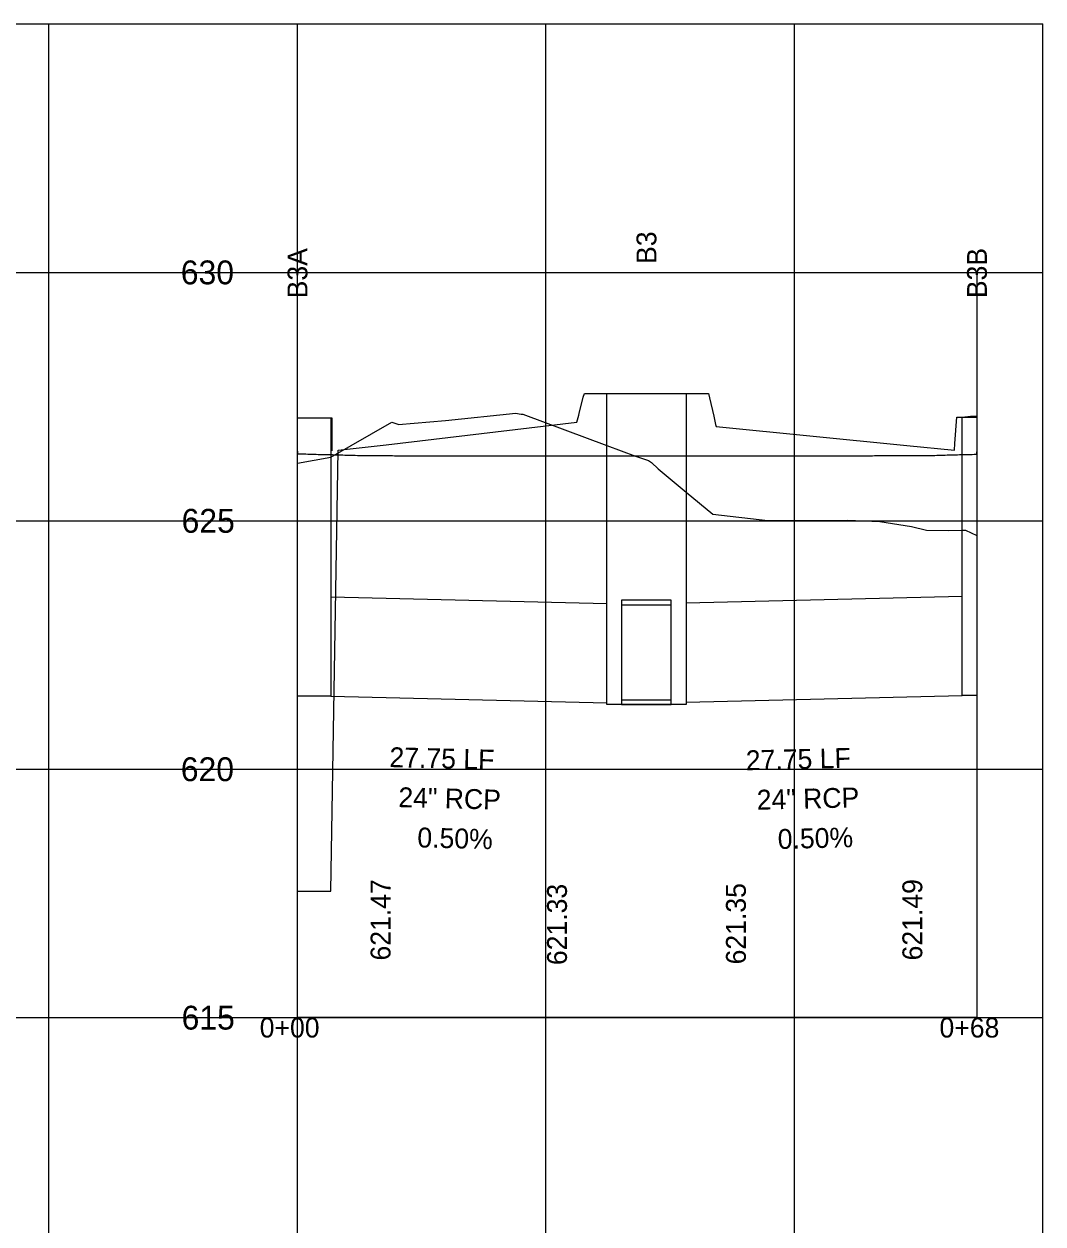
# Model space of a CAD drawing. Extents: x 2254979 to 2278074, y 13790855 to 13792793.
# Drawn here: x 2276971.9 to 2277074.4, y 13792671.8 to 13792792.6 of the extents above; entities that cross this region are included whole.
import ezdxf

# ---------------------------------------------------------------- set-up
doc = ezdxf.new("R2010")
doc.units = 0
for name, color, linetype in [('blank4', 7, 'Continuous'), ('BORD_grid_bottom_major_5int', 7, 'Continuous'), ('D_DRN_PROF_HGL', 7, 'Continuous'), ('D_PROF_1', 7, 'Continuous'), ('D_PROF_NOTES_1', 7, 'Continuous'), ('Default', 7, 'Continuous'), ('Drain_PipeInside', 7, 'Continuous'), ('E_Terrain', 7, 'Continuous'), ('Inlet', 7, 'Continuous'), ('z - Construction', 7, 'Continuous')]:
    doc.layers.add(name, color=color, linetype=linetype)

msp = doc.modelspace()

# ---------------------------------------------------------------- linework, layer by layer
at = {"layer": 'blank4'}
msp.add_lwpolyline([(2276999.4, 13792692.6), (2276999.4, 13792767.6), (2277067.76, 13792767.6), (2277067.76, 13792692.6)], close=True, dxfattribs=at)
at = {"layer": 'BORD_grid_bottom_major_5int'}
for p, q in [((2276749.4, 13792792.6), (2277074.4, 13792792.6)), ((2276974.4, 13792492.6), (2276974.4, 13792792.6)), ((2276999.4, 13792492.6), (2276999.4, 13792792.6)), ((2277024.4, 13792492.6), (2277024.4, 13792792.6)), ((2277049.4, 13792492.6), (2277049.4, 13792792.6)), ((2277074.4, 13792492.6), (2277074.4, 13792792.6)), ((2276749.4, 13792767.6), (2277074.4, 13792767.6)), ((2276749.4, 13792742.6), (2277074.4, 13792742.6)), ((2276749.4, 13792717.6), (2277074.4, 13792717.6)), ((2276749.4, 13792692.6), (2277074.4, 13792692.6))]:
    msp.add_line(p, q, dxfattribs=at)
at = {"layer": 'D_DRN_PROF_HGL'}
msp.add_line((2277034.51, 13792749.13), (2277034.51, 13792749.13), dxfattribs=at)
for points in [[(2276999.4, 13792749.62), (2276999.4, 13792749.35), (2276999.61, 13792749.34), (2276999.82, 13792749.34), (2277000.03, 13792749.33), (2277000.23, 13792749.33), (2277000.44, 13792749.32), (2277000.65, 13792749.32), (2277000.86, 13792749.31), (2277001.07, 13792749.3), (2277001.27, 13792749.3), (2277001.48, 13792749.29), (2277001.69, 13792749.29), (2277001.9, 13792749.28), (2277002.1, 13792749.28), (2277002.31, 13792749.27), (2277002.52, 13792749.27), (2277002.73, 13792749.26), (2277002.93, 13792749.26), (2277003.14, 13792749.25), (2277003.35, 13792749.25), (2277003.56, 13792749.24), (2277003.77, 13792749.23), (2277003.97, 13792749.23), (2277004.18, 13792749.22), (2277004.39, 13792749.22), (2277004.6, 13792749.21), (2277004.8, 13792749.21), (2277005.01, 13792749.2), (2277005.22, 13792749.2), (2277005.43, 13792749.19), (2277005.64, 13792749.19), (2277005.84, 13792749.18), (2277006.05, 13792749.18), (2277006.26, 13792749.17), (2277006.47, 13792749.16), (2277006.67, 13792749.16), (2277006.88, 13792749.16), (2277007.09, 13792749.16), (2277007.3, 13792749.16), (2277007.5, 13792749.16), (2277007.71, 13792749.16), (2277007.92, 13792749.16), (2277008.13, 13792749.16), (2277008.34, 13792749.16), (2277008.54, 13792749.16), (2277008.75, 13792749.16), (2277008.96, 13792749.16), (2277009.17, 13792749.15), (2277009.37, 13792749.15), (2277009.58, 13792749.15), (2277009.79, 13792749.15), (2277010, 13792749.15), (2277010.21, 13792749.15), (2277010.41, 13792749.15), (2277010.62, 13792749.15), (2277010.83, 13792749.15), (2277011.04, 13792749.15), (2277011.24, 13792749.15), (2277011.45, 13792749.15), (2277011.66, 13792749.15), (2277011.87, 13792749.15), (2277012.07, 13792749.15), (2277012.28, 13792749.15), (2277012.49, 13792749.15), (2277012.7, 13792749.15), (2277012.91, 13792749.15), (2277013.11, 13792749.15), (2277013.32, 13792749.15), (2277013.53, 13792749.15), (2277013.74, 13792749.15), (2277013.94, 13792749.15), (2277014.15, 13792749.15), (2277014.36, 13792749.15), (2277014.57, 13792749.15), (2277014.78, 13792749.15), (2277014.98, 13792749.15), (2277015.19, 13792749.15), (2277015.4, 13792749.15), (2277015.61, 13792749.15), (2277015.81, 13792749.15), (2277016.02, 13792749.15), (2277016.23, 13792749.15), (2277016.44, 13792749.15), (2277016.64, 13792749.15), (2277016.85, 13792749.15), (2277017.06, 13792749.15), (2277017.27, 13792749.15), (2277017.48, 13792749.15), (2277017.68, 13792749.15), (2277017.89, 13792749.15), (2277018.1, 13792749.15), (2277018.31, 13792749.15), (2277018.51, 13792749.15), (2277018.72, 13792749.15), (2277018.93, 13792749.15), (2277019.14, 13792749.15), (2277019.34, 13792749.15), (2277019.55, 13792749.15), (2277019.76, 13792749.15), (2277019.97, 13792749.14), (2277020.18, 13792749.14), (2277020.38, 13792749.14), (2277020.59, 13792749.14), (2277020.8, 13792749.14), (2277021.01, 13792749.14), (2277021.21, 13792749.14), (2277021.42, 13792749.14), (2277021.63, 13792749.14), (2277021.84, 13792749.14), (2277022.05, 13792749.14), (2277022.25, 13792749.14), (2277022.46, 13792749.14), (2277022.67, 13792749.14), (2277022.88, 13792749.14), (2277023.08, 13792749.14), (2277023.29, 13792749.14), (2277023.5, 13792749.14), (2277023.71, 13792749.14), (2277023.91, 13792749.14), (2277024.12, 13792749.14), (2277024.33, 13792749.14), (2277024.54, 13792749.14), (2277024.75, 13792749.14), (2277024.95, 13792749.14), (2277025.16, 13792749.14), (2277025.37, 13792749.14), (2277025.58, 13792749.14), (2277025.78, 13792749.14), (2277025.99, 13792749.14), (2277026.2, 13792749.14), (2277026.41, 13792749.14), (2277026.62, 13792749.14), (2277026.82, 13792749.14), (2277027.03, 13792749.14), (2277027.24, 13792749.14), (2277027.45, 13792749.14), (2277027.65, 13792749.14), (2277027.86, 13792749.14), (2277028.07, 13792749.14), (2277028.28, 13792749.14), (2277028.48, 13792749.14), (2277028.69, 13792749.14), (2277028.9, 13792749.14), (2277029.11, 13792749.14), (2277029.32, 13792749.14), (2277029.52, 13792749.14), (2277029.73, 13792749.14), (2277029.94, 13792749.14), (2277030.15, 13792749.14), (2277030.35, 13792749.14), (2277030.56, 13792749.14), (2277030.77, 13792749.13), (2277030.98, 13792749.13), (2277031.18, 13792749.13), (2277031.39, 13792749.13), (2277031.6, 13792749.13), (2277031.81, 13792749.13), (2277032.02, 13792749.13), (2277032.22, 13792749.13), (2277032.43, 13792749.13), (2277032.64, 13792749.13), (2277032.85, 13792749.13), (2277033.05, 13792749.13), (2277033.26, 13792749.13), (2277033.47, 13792749.13), (2277033.68, 13792749.13), (2277033.89, 13792749.13), (2277034.09, 13792749.13), (2277034.3, 13792749.13), (2277034.51, 13792749.13)], [(2277034.51, 13792749.13), (2277034.72, 13792749.13), (2277034.93, 13792749.13), (2277035.13, 13792749.13), (2277035.34, 13792749.13), (2277035.55, 13792749.13), (2277035.76, 13792749.13), (2277035.97, 13792749.13), (2277036.18, 13792749.13), (2277036.39, 13792749.13), (2277036.6, 13792749.13), (2277036.8, 13792749.13), (2277037.01, 13792749.13), (2277037.22, 13792749.13), (2277037.43, 13792749.13), (2277037.64, 13792749.13), (2277037.85, 13792749.13), (2277038.06, 13792749.14), (2277038.26, 13792749.14), (2277038.47, 13792749.14), (2277038.68, 13792749.14), (2277038.89, 13792749.14), (2277039.1, 13792749.14), (2277039.31, 13792749.14), (2277039.52, 13792749.14), (2277039.73, 13792749.14), (2277039.93, 13792749.14), (2277040.14, 13792749.14), (2277040.35, 13792749.14), (2277040.56, 13792749.14), (2277040.77, 13792749.14), (2277040.98, 13792749.14), (2277041.19, 13792749.14), (2277041.39, 13792749.14), (2277041.6, 13792749.14), (2277041.81, 13792749.14), (2277042.02, 13792749.14), (2277042.23, 13792749.14), (2277042.44, 13792749.14), (2277042.65, 13792749.14), (2277042.86, 13792749.14), (2277043.06, 13792749.14), (2277043.27, 13792749.14), (2277043.48, 13792749.14), (2277043.69, 13792749.14), (2277043.9, 13792749.14), (2277044.11, 13792749.14), (2277044.32, 13792749.14), (2277044.52, 13792749.14), (2277044.73, 13792749.14), (2277044.94, 13792749.14), (2277045.15, 13792749.14), (2277045.36, 13792749.14), (2277045.57, 13792749.14), (2277045.78, 13792749.14), (2277045.99, 13792749.14), (2277046.19, 13792749.14), (2277046.4, 13792749.14), (2277046.61, 13792749.14), (2277046.82, 13792749.14), (2277047.03, 13792749.14), (2277047.24, 13792749.14), (2277047.45, 13792749.14), (2277047.65, 13792749.15), (2277047.86, 13792749.15), (2277048.07, 13792749.15), (2277048.28, 13792749.15), (2277048.49, 13792749.15), (2277048.7, 13792749.15), (2277048.91, 13792749.15), (2277049.12, 13792749.15), (2277049.32, 13792749.15), (2277049.53, 13792749.15), (2277049.74, 13792749.15), (2277049.95, 13792749.15), (2277050.16, 13792749.15), (2277050.37, 13792749.15), (2277050.58, 13792749.15), (2277050.78, 13792749.15), (2277050.99, 13792749.15), (2277051.2, 13792749.15), (2277051.41, 13792749.15), (2277051.62, 13792749.15), (2277051.83, 13792749.15), (2277052.04, 13792749.15), (2277052.25, 13792749.15), (2277052.45, 13792749.15), (2277052.66, 13792749.15), (2277052.87, 13792749.15), (2277053.08, 13792749.15), (2277053.29, 13792749.15), (2277053.5, 13792749.15), (2277053.71, 13792749.15), (2277053.91, 13792749.15), (2277054.12, 13792749.15), (2277054.33, 13792749.15), (2277054.54, 13792749.15), (2277054.75, 13792749.15), (2277054.96, 13792749.15), (2277055.17, 13792749.15), (2277055.38, 13792749.15), (2277055.58, 13792749.15), (2277055.79, 13792749.15), (2277056, 13792749.15), (2277056.21, 13792749.15), (2277056.42, 13792749.15), (2277056.63, 13792749.15), (2277056.84, 13792749.15), (2277057.04, 13792749.15), (2277057.25, 13792749.15), (2277057.46, 13792749.16), (2277057.67, 13792749.16), (2277057.88, 13792749.16), (2277058.09, 13792749.16), (2277058.3, 13792749.16), (2277058.51, 13792749.16), (2277058.71, 13792749.16), (2277058.92, 13792749.16), (2277059.13, 13792749.16), (2277059.34, 13792749.16), (2277059.55, 13792749.16), (2277059.76, 13792749.16), (2277059.97, 13792749.16), (2277060.17, 13792749.16), (2277060.38, 13792749.16), (2277060.59, 13792749.16), (2277060.8, 13792749.16), (2277061.01, 13792749.16), (2277061.22, 13792749.16), (2277061.43, 13792749.16), (2277061.64, 13792749.16), (2277061.84, 13792749.16), (2277062.05, 13792749.16), (2277062.26, 13792749.16), (2277062.47, 13792749.17), (2277062.68, 13792749.17), (2277062.89, 13792749.18), (2277063.1, 13792749.18), (2277063.3, 13792749.19), (2277063.51, 13792749.19), (2277063.72, 13792749.2), (2277063.93, 13792749.2), (2277064.14, 13792749.21), (2277064.35, 13792749.21), (2277064.56, 13792749.22), (2277064.77, 13792749.23), (2277064.97, 13792749.23), (2277065.18, 13792749.24), (2277065.39, 13792749.24), (2277065.6, 13792749.25), (2277065.81, 13792749.25), (2277066.02, 13792749.26), (2277066.23, 13792749.26), (2277066.43, 13792749.27), (2277066.64, 13792749.27), (2277066.85, 13792749.28), (2277067.06, 13792749.29), (2277067.27, 13792749.29), (2277067.48, 13792749.3), (2277067.69, 13792749.3), (2277067.76, 13792749.3), (2277067.76, 13792749.54)]]:
    msp.add_lwpolyline(points, dxfattribs=at)
at = {"layer": 'D_PROF_1'}
for points in [[(2276999.4, 13792705.33), (2277002.76, 13792705.33), (2277002.76, 13792705.33), (2277003.51, 13792749.7), (2277008.31, 13792750.26), (2277027.51, 13792752.52), (2277027.69, 13792753.23), (2277027.74, 13792753.41), (2277028.15, 13792755.03), (2277028.26, 13792755.43), (2277030.51, 13792755.43), (2277030.51, 13792755.43), (2277034.51, 13792755.43), (2277034.51, 13792755.43), (2277038.26, 13792755.43), (2277038.51, 13792755.43), (2277038.51, 13792755.43), (2277040.76, 13792755.43), (2277040.86, 13792754.97), (2277041.28, 13792753.12), (2277041.46, 13792752.3), (2277041.51, 13792752.1), (2277060.71, 13792750.18), (2277065.51, 13792749.7), (2277065.55, 13792750.37), (2277065.74, 13792753.03), (2277065.84, 13792753.03), (2277066.26, 13792753.03), (2277066.26, 13792753.03), (2277066.26, 13792753.03), (2277067.11, 13792753.12), (2277067.76, 13792753.18)], [(2276999.62, 13792752.95), (2277002.85, 13792752.95), (2277002.85, 13792749.63)]]:
    msp.add_lwpolyline(points, dxfattribs=at)
at = {"layer": 'Drain_PipeInside'}
for p, q in [((2277002.76, 13792734.96), (2277030.51, 13792734.27)), ((2277038.51, 13792734.34), (2277066.26, 13792735.03)), ((2277002.76, 13792724.96), (2277030.51, 13792724.27)), ((2277038.51, 13792724.34), (2277066.26, 13792725.03))]:
    msp.add_line(p, q, dxfattribs=at)
for points in [[(2277032.01, 13792724.6), (2277037.01, 13792724.6), (2277037.01, 13792734.6), (2277032.01, 13792734.6)], [(2277032.01, 13792724.1), (2277037.01, 13792724.1), (2277037.01, 13792734.1), (2277032.01, 13792734.1)]]:
    msp.add_lwpolyline(points, close=True, dxfattribs=at)
at = {"layer": 'E_Terrain'}
msp.add_lwpolyline([(2276999.4, 13792748.4), (2277002.76, 13792749.02), (2277002.76, 13792749.02), (2277008.89, 13792752.54), (2277009.49, 13792752.32), (2277009.56, 13792752.3), (2277014.29, 13792752.71), (2277021.38, 13792753.43), (2277021.71, 13792753.36), (2277021.92, 13792753.33), (2277022.08, 13792753.33), (2277030.51, 13792750.19), (2277030.51, 13792750.19), (2277033.42, 13792749.1), (2277034.51, 13792748.74), (2277034.51, 13792748.74), (2277034.71, 13792748.68), (2277035.03, 13792748.48), (2277035.7, 13792747.83), (2277038.51, 13792745.5), (2277038.51, 13792745.5), (2277041.18, 13792743.27), (2277046.71, 13792742.62), (2277054.73, 13792742.66), (2277057.98, 13792742.52), (2277061.17, 13792742.02), (2277062.68, 13792741.67), (2277064.92, 13792741.62), (2277066.26, 13792741.65), (2277066.26, 13792741.65), (2277066.61, 13792741.66), (2277067.76, 13792741.12)], dxfattribs=at)
at = {"layer": 'Inlet'}
for points in [[(2277030.51, 13792755.43), (2277038.51, 13792755.43), (2277038.51, 13792724.1), (2277030.51, 13792724.1)], [(2276999.4, 13792752.95), (2277002.76, 13792752.95), (2277002.76, 13792724.96), (2276999.4, 13792724.96)], [(2277066.26, 13792753.03), (2277067.76, 13792753.03), (2277067.76, 13792725.03), (2277066.26, 13792725.03)]]:
    msp.add_lwpolyline(points, close=True, dxfattribs=at)
at = {"layer": 'z - Construction'}
for p, q in [((2276999.4, 13792742.6), (2277067.76, 13792742.6)), ((2276999.4, 13792717.6), (2277067.76, 13792717.6))]:
    msp.add_line(p, q, dxfattribs=at)

# ---------------------------------------------------------------- texts
at = {"layer": 'D_PROF_NOTES_1'}
for s, rotation, p in [('B3', 90, (2277035.51, 13792768.45)), ('B3A', 90, (2277000.4, 13792764.99)), ('B3B', 90, (2277068.76, 13792765.01)), ('27.75 LF', 358.5679, (2277008.63, 13792717.82)), ('27.75 LF', 1.4321, (2277044.53, 13792717.49)), ('24" RCP', 358.5679, (2277009.53, 13792713.79)), ('24" RCP', 1.4321, (2277045.63, 13792713.52)), ('0.50%', 358.5679, (2277011.44, 13792709.74)), ('0.50%', 1.4321, (2277047.74, 13792709.57)), ('621.47', 90, (2277008.76, 13792698.35)), ('621.49', 90, (2277062.26, 13792698.36)), ('621.33', 90, (2277026.51, 13792697.89)), ('621.35', 90, (2277044.51, 13792697.96))]:
    msp.add_text(s, height=2, rotation=rotation, dxfattribs=at).set_placement(p)
at = {"layer": 'Default'}
for s, height, p in [('630', 2.4, (2276987.66, 13792766.4)), ('625', 2.4, (2276987.74, 13792741.4)), ('620', 2.4, (2276987.66, 13792716.4)), ('615', 2.4, (2276987.74, 13792691.4)), ('0+00', 2, (2276995.6, 13792690.6)), ('0+68', 2, (2277063.99, 13792690.6))]:
    msp.add_text(s, height=height, dxfattribs=at).set_placement(p)

doc.saveas('drawing.dxf')
